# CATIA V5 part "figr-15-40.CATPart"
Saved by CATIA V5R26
Part number: Part1
Bounding box of the stored display mesh (mm): x -55.204 to 69.266, y -33.79 to 44.107, z 0 to 118.408
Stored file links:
  D:\_Deepak\CATIA\CATIA V5-6R2016_Deepak\Resources\Part files\Partfiles\c15_catia_v5_6r2016_prt\figr-15-40.CATPart
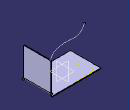
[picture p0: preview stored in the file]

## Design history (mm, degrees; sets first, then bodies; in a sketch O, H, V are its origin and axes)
SheetMetalParameters1: Thickness 2, BendRadius 4, KFactor 0.400515 {= log(min(100,max(20*SheetMetalParameters1.BendRadius,SheetMetalParameters1.Thickness)/SheetMetalParameters1.Thickness))/log(100)/2}, ReliefRadialLength 1, ReliefAxialLength 2, MinimumBendRadius 0
Body1 (main body)
  Sketch1 on xy-plane, origin (0, 0, 0), H (1, 0, 0), V (0, 1, 0)
    line L1 (-55.2037, 44.1067) -> (69.266, 44.1067)
    line L2 (69.266, 44.1067) -> (69.266, -33.7896)
    line L3 (69.266, -33.7896) -> (-55.2037, -33.7896)
    line L4 (-55.2037, -33.7896) -> (-55.2037, 44.1067)
    horizontal: L1 H, L3 H
    vertical: L2 V, L4 V
  Wall1: Thickness 2, Profile Sketch1, OffsetValue 0
  d_NewWallOnEdge1: NewWallOnEdge_Length 77.8964, NewWallOnEdge_HeightLimitOffset 0, NewWallOnEdge_WidthOffset1 -4, NewWallOnEdge_WidthOffset2 -4, NewWallOnEdge_Angle 90, NewWallOnEdge_BendRadiusValue 4 {= SheetMetalParameters1.BendRadius}, NewWallOnEdge_BendTable SheetMetalParameters1, NewWallOnEdge_GapValue 0, NewWallOnEdge_Edge edge [face of Wall1 | face of Wall1], KFacteur 0.400515 {= log(min(100,max(20*d_NewWallOnEdge1.Radius,SheetMetalParameters1.Thickness)/SheetMetalParameters1.Thickness))/log(100)/2}
  Sketch2 on face of d_NewWallOnEdge1, origin (0, 40.1067, 0), H (-1, 0, 0), V (0, 0, 1)
    spline S1 through (-69.266, 77.8964) (-67.9767, 84.9607) (-48.7678, 98.5965) (6.1586, 103.3856) (17.3621, 118.4076)
    reference projected line E1 (-69.266, 6) -> (-69.266, 77.8964) from edge [face of d_NewWallOnEdge1 | face of d_NewWallOnEdge1]
    reference projected line E2 (-69.266, 6) -> (-69.266, 77.8964) from edge [face of d_NewWallOnEdge1 | face of d_NewWallOnEdge1]
    reference projected point E3 (-69.266, 77.8964) from vertex [face of d_NewWallOnEdge1 | face of d_NewWallOnEdge1 | face of d_NewWallOnEdge1]
    point P1 (-69.266, 77.8964)
    coincidence: P1 E1, P1 E3
    tangency: S1 E2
